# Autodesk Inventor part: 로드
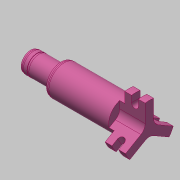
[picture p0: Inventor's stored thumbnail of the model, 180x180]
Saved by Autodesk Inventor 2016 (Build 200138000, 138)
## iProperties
Created: 2020-02
Part Number: 로드
Material: 강철, 연강
Document SubType Name: Modeling
Designer: mduedu
Density: 1 g/cm^3
Appearance: 분홍색
Author: mduedu
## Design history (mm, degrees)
sketch "스케치1"
  geometry: L1 (0, 0)-(-12, 0); L2 (-12, 0)-(-12, 15); L3 (-12, 15)-(0, 15); L4 (0, 15)-(0, 0); L5 (-12, 0)-(-52, 0); L6 (-52, 0)-(-52, 9); L7 (-52, 9)-(-12, 9); L8 (-12, 9)-(-12, 0); L9 (-52, 0)-(-70, 0); L10 (-70, 0)-(-70, 6); L11 (-70, 6)-(-52, 6); L12 (-52, 6)-(-52, 0)
  constraints: 24 end point, 6 parallel, 3 horizontal, 3 perpendicular
  dimensions: "d0" = 70 distance between parallel lines of L4 L10; "d2" = 18 distance of L10.end L11.end; "d3" = 40 distance of L6.end L7.end; "d4" = 12 diameter of L11 L9; "d5" = 18 diameter of L7 L5; "d6" = 30 diameter of L3 L1
revolve "회전1" sketch "스케치1" stored, may be unused: angle "d7" = 90 deg
chamfer "모따기1" distance "d8" = 1.4; stored, may be unused: second distance "d9" = 2, angle "d10" = 15 deg
fillet "모깎기1" dims "d11" = 3
chamfer "모따기2" distance "d12" = 1.4; stored, may be unused: second distance "d13" = 2, angle "d14" = 15 deg
fillet "모깎기2" dims "d15" = 3
sketch "스케치2"
  geometry: L1 (50.981, 8.898)-(52, 8.625) reference; L2 (52, 8.625)-(52, 6) reference; L3 (52, 6)-(68.205, 6) reference; L4 (68.981, 5.898)-(70, 5.625) reference; L5 (70, 5.625)-(70, -5.625) reference; L6 (70, -5.625)-(68.981, -5.898) reference; L7 (68.205, -6)-(52, -6) reference; L8 (52, -6)-(52, -8.625) reference; L9 (52, -8.625)-(50.981, -8.898) reference; L10 (50.205, -9)-(12, -9) reference; L11 (12, -9)-(12, -15) reference; L12 (12, -15)-(0, -15) reference; L13 (0, -15)-(0, 15) reference; L14 (0, 15)-(12, 15) reference; L15 (12, 15)-(12, 9) reference; L16 (12, 9)-(50.205, 9) reference; L17 (0, 0)-(70, 0); L18 (65, 6)-(66.15, 6); L19 (66.15, 6)-(66.15, 5.75); L20 (66.15, 5.75)-(65, 5.75); L21 (65, 5.75)-(65, 6); A1 r 3 centre (50.205, 6) between (50.981, 8.898) and (50.205, 9) reference; A2 r 3 centre (68.205, 3) between (68.981, 5.898) and (68.205, 6) reference; A3 r 3 centre (68.205, -3) between (68.205, -6) and (68.981, -5.898) reference; A4 r 3 centre (50.205, -6) between (50.205, -9) and (50.981, -8.898) reference
  constraints: 10 end point, 2 parallel, 1 horizontal, 1 midpoint, 1 perpendicular, 1 point on line
  dimensions: "d16" = 13 distance between parallel lines of L21 L2; "d17" = 1.15 distance of L18.start L18.end; "d18" = 11.5 diameter of L20 L17
revolve "회전2" sketch "스케치2" stored, may be unused: angle "d19" = 90 deg
sketch "스케치3"
  geometry: L1 (0, 0)-(-15, 0); L2 (0, 0)-(7.5, -12.99); L3 (0, 0)-(7.5, 12.99); L4 (-1.443, -2.5)-(-14.79, -2.5); L5 (-1.443, 2.5)-(-14.79, 2.5); L6 (-1.443, -2.5)-(5.23, -14.059); L7 (2.887, 0)-(9.56, -11.559); L8 (2.887, 0)-(9.56, 11.559); L9 (-1.443, 2.5)-(5.23, 14.059); C1 r 15 at (0, 0) reference; 1 further point
  constraints: 18 end point, 6 parallel, 1 coincident, 1 horizontal, 15 other
  dimensions: "d20" = 120 deg angle of L2 L1; "d21" = 120 deg angle of L3 L1; "d22" = 5 distance between parallel lines of L5 L4; "d24" = 5 distance between parallel lines of L7 L6; "d25" = 5 distance between parallel lines of L9 L8
extrude "돌출1" cut sketch "스케치3" distance "d26" = 15; taper "d27" = 0 deg
fillet "모깎기3" dims "d28" = 5
sketch "스케치4"
  geometry: L1 (4, 21)-(8, 21); L2 (8, 21)-(8, 11); L3 (8, 11)-(4, 11); L4 (4, 11)-(4, 21); 2 further points
  constraints: 8 end point, 2 parallel, 1 horizontal, 1 horizontal alignment, 1 midpoint, 1 perpendicular, 2 other
  dimensions: "d29" = 11 distance from line of L3 point (0, 0); "d30" = 4 distance of L1.start L1.end; "d31" = 6 horizontal distance of point (6, 11) point (0, 0); "d32" = 10 distance between parallel lines of L1 L3
extrude "돌출2" cut sketch "스케치4" stored distance "d33" = 15; taper "d34" = 0 deg
node "솔리드1"
pattern_circular "원형 패턴1" dims angle "d36" = 360 deg
node "투영된 루프1"
node "절단 모서리 투영1"
